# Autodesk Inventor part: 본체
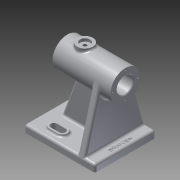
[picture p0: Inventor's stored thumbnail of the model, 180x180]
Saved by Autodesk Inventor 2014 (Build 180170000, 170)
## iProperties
Created: 2019-10
Part Number: 본체
Material: Aluminum 6061
Document SubType Name: Modeling
Designer: kh
Density: 2.71 g/cm^3
Appearance: Aluminum - Flat
Mass: 588.619 g
Surface Area: 540.35 cm^2
Volume: 217.202 cm^3
Author: kh
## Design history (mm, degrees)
sketch "Sketch1"
  geometry: L1 (-50, 43)-(50, 43); L2 (50, 43)-(50, -43); L3 (50, -43)-(-50, -43); L4 (-50, -43)-(-50, 43); L5 (-50, 43)-(50, -43); L6 (50, 43)-(-50, -43); 1 further point
  constraints: 12 end point, 2 midpoint, 2 parallel, 1 horizontal, 1 perpendicular
  dimensions: "d0" = 100 distance of L1.start L1.end; "d1" = 86 distance of L1.end L2.end
extrude "Extrusion1" new body sketch "Sketch1" distance "d2" = 10; taper "d3" = 0 deg
sketch "Sketch2"
  geometry: L1 (-24, 27)-(-12, 27); L2 (-24, 34)-(-12, 34); L3 (-12, 20)-(-24, 20); L4 (-50, 43)-(-50, -43) reference; L5 (50, 43)-(-50, 43) reference; L6 (0, 0)-(-50, 0); L7 (-24, -27)-(-12, -27); L8 (-24, -34)-(-12, -34); L9 (-12, -20)-(-24, -20); A1 r 7 centre (-24, 27) between (-24, 34) and (-24, 20); A2 r 7 centre (-12, 27) between (-12, 20) and (-12, 34); A3 r 7 centre (-24, -27) between (-24, -20) and (-24, -34); A4 r 7 centre (-12, -27) between (-12, -34) and (-12, -20); 2 further points
  constraints: 18 end point, 8 point on circle, 7 symmetric about line, 4 centre point, 4 tangent, 2 midpoint, 1 horizontal, 1 parallel, 2 other
  dimensions: "d4" = 12 distance of L2.start L2.end; "d5" = 7 radius of A2; "d6" = 26 distance from line of L4 L2.start; "d7" = 16 distance from line of L5 point (-18, 27)
extrude "Extrusion2" join sketch "Sketch2" distance "d8" = 3; taper "d9" = 0 deg
sketch "Sketch3"
  geometry: L1 (32, 86)-(-50, 86); L2 (32, 86)-(32, 107); L3 (32, 107)-(-50, 107); L4 (-50, 107)-(-50, 86); L5 (32, 100.5)-(-30, 100.5); L6 (-30, 100.5)-(-30, 97.5); L7 (-30, 97.5)-(-50, 97.5); L8 (-50, 0)-(50, 0) reference; L9 (-50, 0)-(-50, 10) reference; 1 further point
  constraints: 14 end point, 4 perpendicular, 2 parallel, 2 point on line, 1 collinear, 1 horizontal
  dimensions: "d13" = 42 diameter of L3 L1; "d14" = 29 diameter of L5 L1; "d15" = 23 diameter of L7 L1; "d16" = 86 distance between parallel lines of L8 L1; "d17" = 82 distance of L2.end L3.end; "d18" = 62 distance between parallel lines of L2 L6
revolve "Revolution1" sketch "Sketch3" stored, may be unused: angle "d19" = 90 deg
workplane "Work Plane2"
  workplane "Work Plane1"
sketch "Sketch4"
  geometry: L1 (-41, 21)-(-41, -21) reference; L2 (-41, 0)-(30.519, 0); C1 r 11 at (-16, 0); 1 further point
  constraints: 2 end point, 1 centre point, 1 midpoint, 1 perpendicular, 1 point on line
  dimensions: "d21" = 22 diameter of C1; "d22" = 25 distance from line of L1 C1.centre
extrude "Extrusion3" join sketch "Sketch4" stored distance "d23" = 3; taper "d24" = 0 deg
hole "Hole1" diameter "d27" = 4.917; stored, may be unused: countersink angle "d31" = 90 deg, drill point angle "d33" = 0 deg; dims "d28" = 6, "d29" = 14, "d30" = 4, "d32" = 10, "d34" = 10, "d35" = 10
workplane "Work Plane3"
fillet "Fillet1" dims "d37" = 3
fillet "Fillet2" dims "d38" = 3
sketch "Sketch5"
  geometry: L1 (-42.896, 7.783)-(-20.272, 91.48); L2 (0, 0)-(0, 35.865); L3 (42.896, 7.783)-(20.272, 91.48); L4 (-40, 10)-(40, 10) reference; L5 (-42.896, 7.783)-(42.896, 7.783); A1 r 3 centre (-40, 7) between (-40, 10) and (-43, 7) reference; A2 r 3 centre (40, 7) between (43, 7) and (40, 10) reference; A3 r 21 centre (0, 86) between (-20.272, 91.48) and (20.272, 91.48); 1 further point
  constraints: 8 end point, 3 point on circle, 2 symmetric about line, 1 centre point, 1 coincident, 1 parallel, 1 tangent, 1 vertical, 4 other
extrude "Extrusion4" join sketch "Sketch5" distance "d39" = 10; taper "d40" = 0 deg
sketch "Sketch6"
  geometry: L1 (47, 10)-(-25, 10) reference; L2 (35, 10)-(18.524, 55.267); L3 (50, 0)-(50, 7) reference; 1 further point
  constraints: 2 end point, 1 point on line
  dimensions: "d41" = 15 distance from line of L3 L2.start; "d42" = 70 deg angle of L1 L2
feature "Rib1" sketch "Sketch6" dims "d43" = 1, "d44" = 10, "d45" = 0, "d46" = 0, "d47" = 1, "d48" = 1
sketch "Sketch7" dims "d49" = 36
  geometry: L1 (0, 0)-(-18, 0); C1 r 11.5 at (0, 0) reference; 2 further points
  constraints: 2 coincident, 2 end point, 1 horizontal, 1 horizontal alignment, 2 other
hole "Hole2" sketch "Sketch7" at (-18, 0) diameter "d50" = 2.459; stored, may be unused: countersink angle "d54" = 90 deg, drill point angle "d56" = 118 deg; dims "d51" = 8, "d52" = 14, "d53" = 4, "d55" = 10
pattern_circular "Circular Pattern1" dims angle "d58" = 360 deg
workplane "Work Plane4"
mirror "Mirror1"
workplane "Work Plane5"
sketch "Sketch8"
  geometry: L1 (40.598, -16.592)-(40.598, 16.592); L2 (40.598, 16.592)-(45.402, 16.592); L3 (45.402, 16.592)-(45.402, -16.592); L4 (45.402, -16.592)-(40.598, -16.592); L5 (45.402, -16.592)-(40.598, 16.592); L6 (-47, -43)-(47, -43) reference; L7 (50, -40)-(50, 40) reference; 2 further points
  constraints: 2 end point, 1 midpoint, 2 other
  dimensions: "d61" = 43 distance from line of L6 point (43, 0); "d62" = 7 distance from line of L7 point (43, 0)
emboss "Emboss1" sketch "Sketch8" dims "d0" = 100, "d1" = 86, "d4" = 12, "d5" = 7, "d6" = 26, "d7" = 16, "d63" = 0.5, "d64" = 0
sketch "Sketch9"
  geometry: L1 (-24, -27)-(-12, -27); L2 (-24, -31.5)-(-12, -31.5); L3 (-12, -22.5)-(-24, -22.5); L4 (0, 0)-(-26.131, 0); L5 (-24, 31.5)-(-12, 31.5); L6 (-12, 22.5)-(-24, 22.5); A1 r 7 centre (-24, -27) between (-24, -20) and (-24, -34) reference; A2 r 7 centre (-12, -27) between (-12, -34) and (-12, -20) reference; A3 r 4.5 centre (-24, -27) between (-24, -22.5) and (-24, -31.5); A4 r 4.5 centre (-12, -27) between (-12, -31.5) and (-12, -22.5); A5 r 4.5 centre (-12, 27) between (-12, 22.5) and (-12, 31.5); A6 r 4.5 centre (-24, 27) between (-24, 31.5) and (-24, 22.5); 1 further point
  constraints: 14 end point, 8 point on circle, 6 symmetric about line, 4 centre point, 4 tangent, 2 parallel, 1 horizontal, 1 midpoint, 2 other
  dimensions: "d65" = 4.5 radius of A4
extrude "Extrusion5" cut sketch "Sketch9" stored distance "d66" = 10; taper "d67" = 0 deg
fillet "Fillet3" dims "d68" = 3
chamfer "Chamfer1" distance "d69" = 1; stored, may be unused: second distance "d70" = 2, angle "d71" = 45 deg
fillet "Fillet4" dims "d72" = 3
fillet "Fillet5" dims "d73" = 3
fillet "Fillet6" dims "d74" = 3
fillet "Fillet7" dims "d75" = 3
body "Solid1"
other parameters: "d20" = 3, "d36" = 35, "d60" = 9.75
